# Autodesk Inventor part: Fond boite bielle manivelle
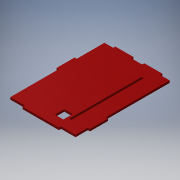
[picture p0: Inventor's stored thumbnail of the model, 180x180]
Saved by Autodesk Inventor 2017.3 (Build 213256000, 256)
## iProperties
Part Number: Fond boite bielle manivelle
Material: Générique
Document SubType Name: Modeling
Designer: ficho
Density: 1 g/cm^3
Appearance: Rouge
Author: ficho
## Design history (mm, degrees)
sketch "Esquisse1"
  geometry: L1 (0, 0)-(50, 0); L2 (50, 0)-(50, 3); L3 (0, 0)-(0, 3); L4 (46.5, 18)-(46.5, 118); L5 (46.5, 18)-(49.5, 18); L6 (49.5, 118)-(49.5, 18); L7 (46.5, 118)-(49.5, 118); L8 (73, 19.908)-(70, 19.908); L9 (73, 44.908)-(73, 19.908); L10 (73, 44.908)-(70, 44.908); L11 (50, 3)-(70, 3); L12 (50, 0)-(50, 3); L13 (73, 19.908)-(70, 19.908); L14 (70, 19.908)-(70, 3); L15 (0, 0)-(0, 3); L16 (-20, 3)-(0, 3); L17 (-20, 69.766)-(-23, 69.766); L18 (-20, 69.766)-(-20, 3); L19 (-23, 69.766)-(-23, 94.766); L20 (-23, 69.766)-(-20, 69.766); L21 (-23, 94.766)-(-20, 94.766); L22 (-23, 94.766)-(-20, 94.766); L23 (-20, 133)-(-20, 94.766); L24 (70, 44.908)-(73, 44.908); L25 (70, 133)-(70, 44.908); L26 (-20, 133)-(-8, 133); L27 (-8, 133)-(-8, 136); L28 (17, 133)-(17, 136); L29 (-8, 136)-(17, 136); L30 (-8, 133)-(-8, 136); L31 (17, 133)-(32, 133); L32 (32, 133)-(32, 136); L33 (17, 133)-(17, 136); L34 (57, 133)-(57, 136); L35 (32, 136)-(57, 136); L36 (32, 133)-(32, 136); L37 (57, 133)-(70, 133); L38 (57, 133)-(57, 136)
  constraints: 76 end point
extrude "Extrusion1" new body sketch "Esquisse1" distance "d0" = 3; taper "d1" = 0 deg
sketch "Esquisse2"
  geometry: L1 (46.5, 118)-(49.5, 118) reference; L2 (49.5, 118)-(49.5, 18) reference; L3 (49.5, 18)-(46.5, 18) reference; L4 (46.5, 18)-(46.5, 118) reference; L5 (0, 0)-(50, 0) reference; L6 (50, 0)-(50, 3) reference; L7 (50, 3)-(70, 3) reference; L8 (70, 3)-(70, 19.908) reference; L9 (70, 19.908)-(73, 19.908) reference; L10 (73, 19.908)-(73, 44.908) reference; L11 (73, 44.908)-(70, 44.908) reference; L12 (70, 44.908)-(70, 133) reference; L13 (70, 133)-(57, 133) reference; L14 (57, 133)-(57, 136) reference; L15 (57, 136)-(32, 136) reference; L16 (32, 136)-(32, 133) reference; L17 (32, 133)-(17, 133) reference; L18 (17, 133)-(17, 136) reference; L19 (17, 136)-(-8, 136) reference; L20 (-8, 136)-(-8, 133) reference; L21 (-8, 133)-(-20, 133) reference; L22 (-20, 133)-(-20, 94.766) reference; L23 (-20, 94.766)-(-23, 94.766) reference; L24 (-23, 94.766)-(-23, 69.766) reference; L25 (-23, 69.766)-(-20, 69.766) reference; L26 (-20, 69.766)-(-20, 3) reference; L27 (-20, 3)-(0, 3) reference; L28 (0, 3)-(0, 0) reference; L29 (32.2, 24.88)-(32.2, 13.76) reference; L30 (32.76, 13.3)-(42.41, 13.3) reference; L31 (42.41, 13.3)-(42.82, 13.3) reference; L32 (42.82, 13.3)-(42.82, 25.34) reference; L33 (42.41, 25.34)-(32.76, 25.34) reference; L34 (42.82, 25.34)-(42.41, 25.34) reference; L35 (35.56, 13.3)-(32.66, 13.3) reference; L36 (32.66, 25.34)-(35.56, 25.34) reference; L37 (31.7, 12.8)-(43.32, 12.8); L38 (43.32, 12.8)-(43.32, 25.84); L39 (43.32, 25.84)-(31.7, 25.84); L40 (31.7, 25.84)-(31.7, 12.8); 1 further point
  constraints: 8 end point, 2 parallel, 1 horizontal, 1 perpendicular
  dimensions: "d2" = 0.5 distance between parallel lines of L35 L37; "d3" = 0.5 distance between parallel lines of L39 L33 (= d2); "d4" = 0.5 distance between parallel lines of L40 L29 (= d2); "d5" = 0.5 distance between parallel lines of L38 L32 (= d2)
extrude "Extrusion2" cut sketch "Esquisse2" stored distance "d6" = 10; taper "d7" = 0 deg
node "Solide1"
node "Boucle projetée1"
node "Référence16"
node "Référence17"
node "Référence18"
node "Référence19"
node "Référence20"
node "Référence21"
node "Référence22"
node "Référence23"
node "Référence24"
node "Référence25"
